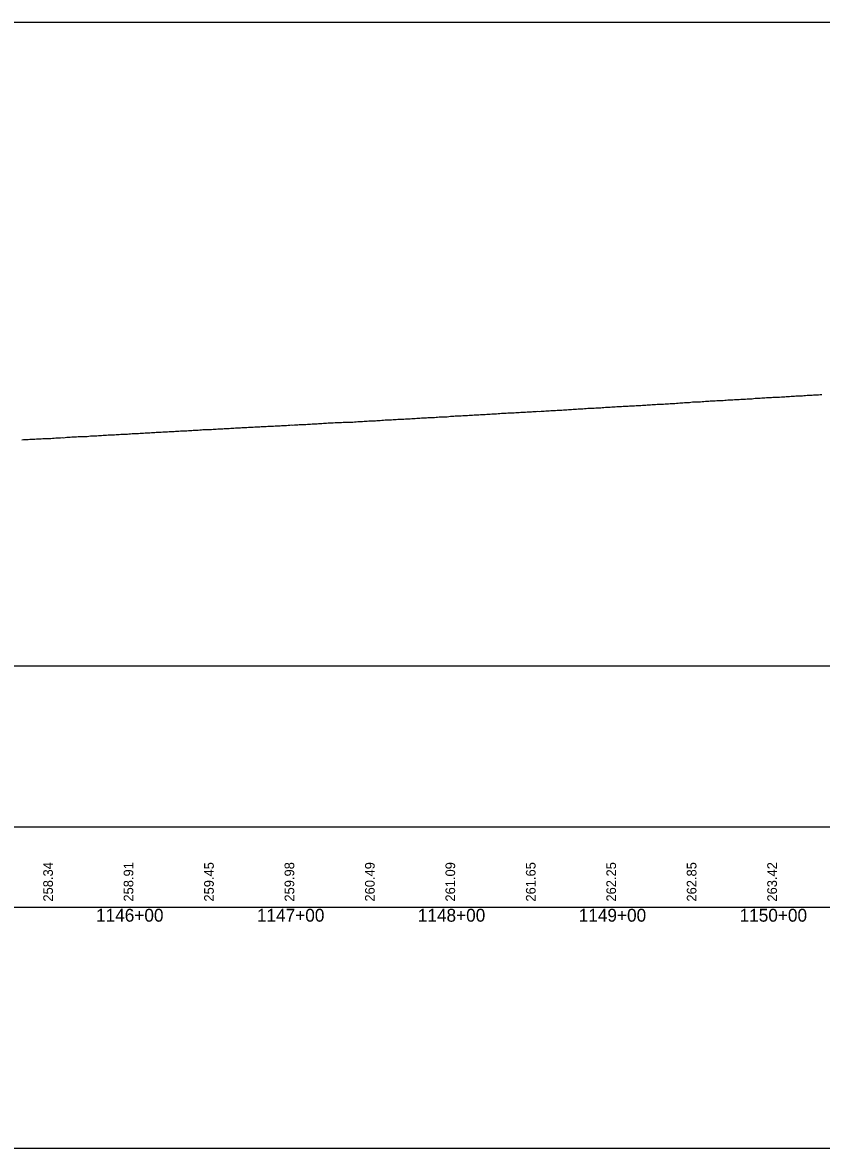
# Model space of a CAD drawing. Extents: x 2898 to 49495, y -15038 to -13538.
# Drawn here: x 3883 to 4380, y -15038 to -14338 of the extents above; entities that cross this region are included whole.
import ezdxf

# ---------------------------------------------------------------- set-up
doc = ezdxf.new("R2010")
doc.units = 0
for name, color, linetype in [('RD_DDB_Profile_EX', 7, 'Continuous'), ('RD_DDB_StaTX', 7, 'Continuous'), ('RD_DDB_StripGrade', 7, 'Continuous'), ('RD_GPK_Profile_Cell', 7, 'Continuous'), ('RD_SHT_ShtClip', 7, 'Continuous')]:
    doc.layers.add(name, color=color, linetype=linetype)

msp = doc.modelspace()

# ---------------------------------------------------------------- linework, layer by layer
at = {"layer": 'RD_DDB_Profile_EX'}
for points in [[(4245.83, -14577.67), (4246.83, -14577.67), (4247.84, -14577.63), (4248.83, -14577.63), (4249.83, -14577.48), (4250.83, -14577.43), (4251.83, -14577.38), (4252.83, -14577.23), (4253.83, -14577.23), (4254.83, -14577.23), (4255.83, -14577.13), (4256.83, -14577.03), (4257.83, -14576.98), (4258.83, -14576.98), (4259.83, -14576.93), (4260.83, -14576.83), (4261.83, -14576.83), (4262.83, -14576.78), (4263.83, -14576.73), (4264.83, -14576.63), (4265.83, -14576.53), (4266.83, -14576.53), (4267.83, -14576.48), (4268.82, -14576.38), (4269.83, -14576.28), (4270.83, -14576.28), (4271.83, -14576.18), (4272.82, -14576.13), (4273.83, -14576.09), (4274.83, -14576.03), (4275.83, -14575.98), (4276.98, -14575.84), (4277.98, -14575.83), (4278.98, -14575.83), (4279.98, -14575.73), (4280.98, -14575.68), (4281.98, -14575.68), (4282.98, -14575.53), (4283.99, -14575.48), (4284.98, -14575.43), (4285.98, -14575.38), (4286.98, -14575.33), (4287.98, -14575.28), (4288.98, -14575.23), (4289.98, -14575.13), (4290.98, -14575.03), (4291.98, -14574.93), (4292.98, -14574.88), (4293.98, -14574.83), (4294.99, -14574.78), (4295.98, -14574.68), (4296.98, -14574.63), (4297.98, -14574.63), (4298.98, -14574.48), (4299.97, -14574.38), (4300.98, -14574.38), (4301.99, -14574.33), (4302.98, -14574.23), (4303.98, -14574.18), (4304.98, -14574.18), (4305.97, -14574.08), (4306.97, -14574.03), (4307.98, -14573.93), (4308.98, -14573.88), (4309.97, -14573.83), (4310.98, -14573.73), (4311.99, -14573.68), (4312.97, -14573.68), (4313.98, -14573.63), (4314.97, -14573.53), (4315.98, -14573.48), (4316.92, -14573.43), (4317.91, -14573.38), (4318.93, -14573.38), (4319.93, -14573.23), (4320.92, -14573.18), (4321.93, -14573.13), (4322.92, -14573.13), (4323.93, -14573.08), (4324.93, -14572.98), (4325.93, -14572.93), (4326.92, -14572.93), (4327.93, -14572.83), (4328.93, -14572.73), (4329.93, -14572.68), (4330.92, -14572.63), (4331.93, -14572.58), (4332.93, -14572.58), (4333.93, -14572.48), (4334.93, -14572.43), (4335.93, -14572.43), (4336.92, -14572.33), (4337.93, -14572.24), (4338.92, -14572.09), (4339.92, -14572.09), (4340.91, -14572.09), (4341.93, -14571.94), (4342.92, -14571.89), (4343.92, -14571.84), (4344.92, -14571.74), (4345.92, -14571.64)], [(4345.92, -14571.64), (4346.92, -14571.59), (4347.92, -14571.59), (4348.92, -14571.54), (4349.92, -14571.44), (4350.92, -14571.34), (4351.92, -14571.34), (4352.92, -14571.39), (4353.92, -14571.29), (4355.21, -14571.24), (4356.21, -14571.19), (4357.21, -14571.09), (4358.21, -14571.04), (4359.21, -14570.94), (4360.21, -14570.89), (4361.22, -14570.84), (4362.21, -14570.79), (4363.21, -14570.74), (4364.21, -14570.64), (4365.21, -14570.64), (4366.21, -14570.59), (4367.2, -14570.49), (4368.21, -14570.49), (4369.2, -14570.44), (4370.21, -14570.29), (4371.2, -14570.24), (4372.21, -14570.19), (4373.21, -14570.19), (4374.21, -14570.14), (4375.21, -14570), (4376.21, -14569.99), (4377.21, -14569.89), (4378.21, -14569.89), (4379.21, -14569.75), (4380.21, -14569.74)], [(4146.5, -14583.56), (4147.5, -14583.51), (4148.5, -14583.37), (4149.5, -14583.27), (4150.5, -14583.21), (4151.49, -14583.12), (4152.5, -14583.06), (4153.49, -14583.01), (4154.49, -14583.01), (4155.5, -14582.96), (4156.15, -14582.92), (4157.14, -14582.82), (4158.16, -14582.76), (4159.15, -14582.71), (4160.15, -14582.71), (4161.15, -14582.61), (4162.15, -14582.61), (4163.15, -14582.51), (4164.15, -14582.41), (4165.15, -14582.41), (4166.15, -14582.36), (4167.15, -14582.27), (4168.15, -14582.16), (4169.15, -14582.16), (4170.15, -14582.11), (4171.15, -14582.06), (4172.14, -14581.96), (4173.15, -14581.91), (4174.15, -14581.87), (4175.14, -14581.81), (4176.15, -14581.72), (4177.14, -14581.67), (4178.14, -14581.67), (4179.15, -14581.57), (4180.15, -14581.47), (4181.14, -14581.42), (4182.15, -14581.37), (4183.14, -14581.37), (4184.14, -14581.32), (4185.14, -14581.22), (4186.15, -14581.12), (4187.14, -14581.12), (4188.15, -14581.07), (4189.14, -14581.02), (4190.14, -14580.92), (4191.15, -14580.92), (4192.14, -14580.82), (4193.15, -14580.67), (4194.15, -14580.67), (4195.15, -14580.67), (4196.14, -14580.67), (4197.15, -14580.57), (4197.77, -14580.52), (4198.77, -14580.52), (4199.77, -14580.42), (4200.77, -14580.27), (4201.77, -14580.32), (4202.77, -14580.32), (4203.77, -14580.17), (4204.77, -14580.22), (4205.77, -14580.12), (4206.77, -14580.07), (4207.77, -14580.02), (4208.77, -14579.92), (4209.77, -14579.92), (4210.77, -14579.87), (4211.77, -14579.77), (4212.77, -14579.72), (4213.77, -14579.62), (4214.77, -14579.57), (4215.77, -14579.52), (4216.77, -14579.47), (4217.77, -14579.42), (4218.77, -14579.42), (4219.77, -14579.27), (4220.76, -14579.22), (4221.77, -14579.22), (4222.76, -14579.07), (4223.77, -14579.02), (4224.77, -14578.97), (4225.77, -14578.87), (4226.77, -14578.82), (4227.78, -14578.77), (4228.77, -14578.67), (4229.78, -14578.62), (4230.77, -14578.67), (4231.77, -14578.57), (4232.77, -14578.47), (4233.77, -14578.37), (4234.77, -14578.32), (4235.77, -14578.32), (4236.77, -14578.27), (4237.83, -14578.17), (4238.84, -14578.12), (4239.84, -14578.07), (4240.83, -14578.02), (4241.83, -14577.97), (4242.84, -14577.92), (4243.84, -14577.82), (4244.83, -14577.72), (4245.83, -14577.67)], [(4046.54, -14588.98), (4047.55, -14588.93), (4048.54, -14588.83), (4049.54, -14588.73), (4050.55, -14588.68), (4051.54, -14588.73), (4052.54, -14588.67), (4053.54, -14588.53), (4054.54, -14588.48), (4055.54, -14588.47), (4056.55, -14588.47), (4057.54, -14588.42), (4058.54, -14588.32), (4059.54, -14588.27), (4060.54, -14588.22), (4061.54, -14588.08), (4062.54, -14588.07), (4063.54, -14588.02), (4064.54, -14587.92), (4065.54, -14587.92), (4066.54, -14587.87), (4067.55, -14587.77), (4068.54, -14587.77), (4069.54, -14587.67), (4070.54, -14587.57), (4071.54, -14587.52), (4072.53, -14587.52), (4073.54, -14587.42), (4074.54, -14587.37), (4075.54, -14587.42), (4076.54, -14587.37), (4077.81, -14587.22), (4078.81, -14587.22), (4079.82, -14587.17), (4080.81, -14587.12), (4081.81, -14587.07), (4082.81, -14587.02), (4083.81, -14586.97), (4084.82, -14586.87), (4085.81, -14586.92), (4086.82, -14586.92), (4087.81, -14586.87), (4088.81, -14586.82), (4089.82, -14586.72), (4090.81, -14586.72), (4091.82, -14586.57), (4092.8, -14586.52), (4093.81, -14586.52), (4094.8, -14586.47), (4095.81, -14586.37), (4096.81, -14586.27), (4097.81, -14586.22), (4098.81, -14586.17), (4099.8, -14586.12), (4100.81, -14586.07), (4101.81, -14586.07), (4102.81, -14586.02), (4103.81, -14585.97), (4104.81, -14585.92), (4105.81, -14585.82), (4106.81, -14585.77), (4107.81, -14585.72), (4108.81, -14585.57), (4109.82, -14585.52), (4110.81, -14585.52), (4111.81, -14585.47), (4112.81, -14585.42), (4113.81, -14585.32), (4114.81, -14585.27), (4115.81, -14585.22), (4116.81, -14585.12), (4117.81, -14585.07), (4118.5, -14585.02), (4119.5, -14585.02), (4120.5, -14584.97), (4121.5, -14584.87), (4122.5, -14584.87), (4123.5, -14584.82), (4124.5, -14584.77), (4125.5, -14584.62), (4126.51, -14584.62), (4127.5, -14584.57), (4128.5, -14584.42), (4129.5, -14584.37), (4130.5, -14584.37), (4131.5, -14584.32), (4132.5, -14584.22), (4133.5, -14584.22), (4134.5, -14584.17), (4135.5, -14584.12), (4136.5, -14584.07), (4137.5, -14583.97), (4138.5, -14583.92), (4139.5, -14583.92), (4140.5, -14583.87), (4141.5, -14583.72), (4142.5, -14583.67), (4143.5, -14583.62), (4144.49, -14583.57), (4145.5, -14583.57), (4146.5, -14583.56)], [(3883.09, -14597.83), (3884.11, -14597.78), (3885.1, -14597.73), (3886.1, -14597.64), (3887.1, -14597.68), (3888.1, -14597.58), (3889.1, -14597.48), (3890.1, -14597.48), (3891.1, -14597.43), (3892.1, -14597.33), (3893.1, -14597.28), (3894.1, -14597.33), (3895.1, -14597.23), (3896.1, -14597.18), (3897.1, -14597.08), (3898.1, -14597.03), (3899.1, -14597.03), (3900.1, -14597.08), (3901.1, -14597.03), (3902.1, -14596.93), (3903.1, -14596.78), (3904.1, -14596.73), (3905.1, -14596.68), (3906.1, -14596.63), (3907.09, -14596.58), (3908.1, -14596.48), (3909.1, -14596.58), (3910.1, -14596.48), (3911.09, -14596.33), (3912.1, -14596.23), (3913.09, -14596.18), (3914.1, -14596.13), (3915.1, -14596.08), (3916.1, -14596.03), (3917.1, -14595.98), (3918.09, -14595.88), (3919.09, -14595.83), (3920.11, -14595.83), (3920.67, -14595.83), (3921.66, -14595.78), (3922.67, -14595.78), (3923.67, -14595.78), (3924.67, -14595.68), (3925.67, -14595.43), (3926.66, -14595.38), (3927.67, -14595.43), (3928.67, -14595.43), (3929.67, -14595.33), (3930.67, -14595.23), (3931.67, -14595.18), (3932.67, -14595.13), (3933.67, -14595.08), (3934.67, -14595.03), (3935.67, -14594.93), (3936.66, -14594.88), (3937.66, -14594.83), (3938.66, -14594.78), (3939.67, -14594.73), (3940.66, -14594.73), (3941.67, -14594.58), (3942.66, -14594.53), (3943.66, -14594.53), (3944.67, -14594.48), (3945.66, -14594.43), (3946.67, -14594.38)], [(3946.67, -14594.38), (3947.67, -14594.33), (3948.67, -14594.28), (3949.67, -14594.18), (3950.66, -14594.08), (3951.67, -14594.03), (3952.67, -14593.98), (3953.66, -14593.88), (3954.66, -14593.88), (3955.66, -14593.88), (3956.66, -14593.78), (3957.66, -14593.73), (3958.66, -14593.68), (3959.66, -14593.63), (3960.66, -14593.63), (3961.66, -14593.58), (3962.66, -14593.53), (3963.67, -14593.43), (3964.66, -14593.28), (3965.67, -14593.28), (3966.66, -14593.23), (3967.66, -14593.18), (3968.67, -14593.13), (3969.66, -14593.08), (3970.66, -14592.98), (3971.66, -14592.93), (3972.66, -14592.88), (3973.66, -14592.83), (3974.66, -14592.78), (3975.66, -14592.64), (3976.66, -14592.63), (3977.66, -14592.63), (3978.66, -14592.49), (3979.66, -14592.43), (3980.66, -14592.48), (3981.66, -14592.38), (3982.66, -14592.33), (3983.66, -14592.23), (3984.66, -14592.23), (3985.66, -14592.23), (3986.66, -14592.09), (3987.66, -14592.08), (3988.65, -14592.03), (3989.66, -14591.94), (3990.65, -14591.93), (3991.66, -14591.88), (3992.66, -14591.83), (3993.66, -14591.78), (3994.66, -14591.68), (3995.66, -14591.58), (3996.66, -14591.53), (3997.66, -14591.48), (3998.92, -14591.43), (3999.92, -14591.38), (4000.91, -14591.38), (4001.91, -14591.28), (4002.91, -14591.28), (4003.92, -14591.18), (4004.92, -14591.13), (4005.91, -14591.08), (4006.92, -14591.03), (4007.91, -14590.98), (4008.92, -14590.93), (4009.91, -14590.88), (4010.91, -14590.83), (4011.92, -14590.78), (4012.91, -14590.73), (4013.91, -14590.68), (4014.91, -14590.63), (4015.91, -14590.53), (4016.92, -14590.48), (4017.92, -14590.43), (4018.91, -14590.38), (4019.91, -14590.33), (4020.91, -14590.28), (4021.91, -14590.28), (4022.91, -14590.23), (4023.91, -14590.13), (4024.92, -14590.03), (4025.91, -14590.03), (4026.92, -14589.93), (4027.91, -14589.83), (4028.91, -14589.78), (4029.91, -14589.78), (4030.91, -14589.73), (4031.91, -14589.68), (4032.91, -14589.63), (4033.91, -14589.58), (4034.91, -14589.53), (4035.91, -14589.48), (4036.91, -14589.43), (4037.53, -14589.38), (4038.53, -14589.38), (4039.54, -14589.37), (4040.54, -14589.28), (4041.54, -14589.18), (4042.54, -14589.13), (4043.54, -14589.13), (4044.54, -14589.08), (4045.55, -14589.02), (4046.54, -14588.98)]]:
    msp.add_lwpolyline(points, dxfattribs=at)
at = {"layer": 'RD_GPK_Profile_Cell'}
msp.add_line((2976.05, -14888.47), (48721.13, -14888.47), dxfattribs=at)
at = {"layer": 'RD_SHT_ShtClip'}
for points in [[(4476.22, -14838.47), (4476.22, -14338.47), (4476.22, -14338.47), (2976.38, -14338.47), (2976.38, -14838.47)], [(2956.38, -14738.47), (4496.05, -14738.47), (4496.05, -15038.47), (2956.38, -15038.47)]]:
    msp.add_lwpolyline(points, close=True, dxfattribs=at)

# ---------------------------------------------------------------- texts
at = {"layer": 'RD_DDB_StaTX'}
for s, p in [('1146+00', (3929.18, -14897.47)), ('1147+00', (4029.18, -14897.47)), ('1148+00', (4129.18, -14897.47)), ('1149+00', (4229.18, -14897.47)), ('1150+00', (4329.18, -14897.47))]:
    msp.add_text(s, height=8, dxfattribs=at).set_placement(p)
at = {"layer": 'RD_DDB_StripGrade'}
for s, p in [('258.34', (3902.38, -14884.98)), ('258.91', (3952.38, -14884.98)), ('259.45', (4002.38, -14884.98)), ('259.98', (4052.38, -14884.98)), ('260.49', (4102.38, -14884.98)), ('261.09', (4152.38, -14884.98)), ('261.65', (4202.38, -14884.98)), ('262.25', (4252.38, -14884.98)), ('262.85', (4302.38, -14884.98)), ('263.42', (4352.38, -14884.98))]:
    msp.add_text(s, height=6, rotation=90, dxfattribs=at).set_placement(p)

doc.saveas('drawing.dxf')
